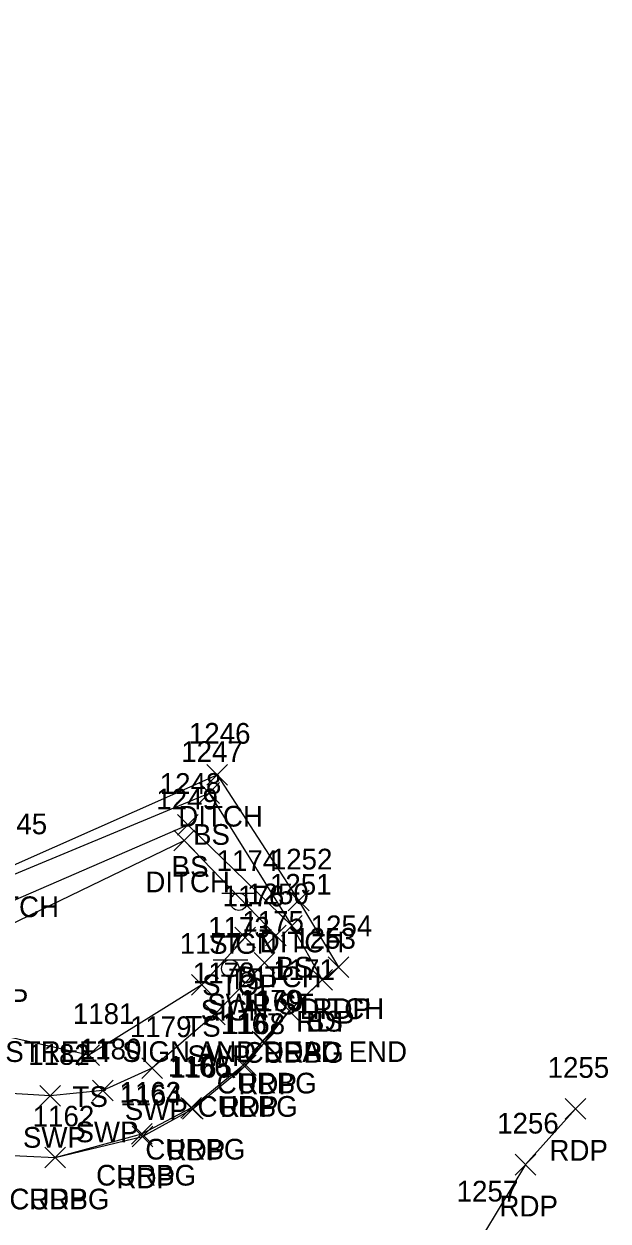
# Model space of a CAD drawing. Extents: x 1688195 to 1692013, y 424605 to 441234.
# Drawn here: x 1691954.3 to 1692010.6, y 439243.2 to 439358.8 of the extents above; entities that cross this region are included whole.
import ezdxf

# ---------------------------------------------------------------- set-up
doc = ezdxf.new("R2010")
doc.units = 0
for name, color, linetype in [('D_A', 7, 'Continuous'), ('D_C', 7, 'Continuous'), ('D_I', 7, 'Continuous'), ('D_TIC', 7, 'Continuous'), ('DD', 7, 'Continuous'), ('L_A', 7, 'Continuous'), ('L_I', 7, 'Continuous'), ('L_TIC', 7, 'Continuous'), ('LELB', 7, 'Continuous'), ('P_A', 7, 'Continuous'), ('P_I', 7, 'Continuous'), ('P_TIC', 7, 'Continuous'), ('PET', 7, 'Continuous'), ('R_A', 7, 'Continuous'), ('R_I', 7, 'Continuous'), ('R_TIC', 7, 'Continuous'), ('RC', 7, 'Continuous'), ('RSW', 7, 'Continuous'), ('S_A', 7, 'Continuous'), ('S_C', 7, 'Continuous'), ('S_I', 7, 'Continuous'), ('SSGN', 7, 'Continuous')]:
    doc.layers.add(name, color=color, linetype=linetype)

msp = doc.modelspace()

# ---------------------------------------------------------------- linework, layer by layer
at = {"layer": 'D_TIC'}
for points in [[(1691971.91, 439285.3), (1691973.91, 439287.3)], [(1691973.91, 439285.3), (1691971.91, 439287.3)], [(1691968.73, 439278.96), (1691970.73, 439280.96)], [(1691970.73, 439278.96), (1691968.73, 439280.96)], [(1691979.77, 439273.16), (1691981.77, 439275.16)], [(1691981.77, 439273.16), (1691979.77, 439275.16)], [(1691977.58, 439269.8), (1691979.58, 439271.8)], [(1691979.58, 439269.8), (1691977.58, 439271.8)], [(1691983.62, 439266.72), (1691985.62, 439268.72)], [(1691985.62, 439266.72), (1691983.62, 439268.72)]]:
    msp.add_lwpolyline(points, dxfattribs=at)
at = {"layer": 'DD'}
for points in [[(1691845, 439386.65), (1691846.96, 439371.91), (1691853.76, 439362.04), (1691874.03, 439339.66), (1691896.1, 439318.91), (1691934.44, 439282.93), (1691949.73, 439270.29), (1691969.73, 439279.96), (1691978.58, 439270.8)], [(1691849.48, 439383.4), (1691851.48, 439372.69), (1691857.96, 439364.8), (1691877.63, 439343.99), (1691899.36, 439321.57), (1691937.96, 439287.21), (1691947.81, 439278.16), (1691953.23, 439277.56), (1691972.91, 439286.3), (1691980.77, 439274.16), (1691984.62, 439267.72)]]:
    msp.add_lwpolyline(points, dxfattribs=at)
at = {"layer": 'L_TIC'}
for points in [[(1691971.13, 439283.54), (1691973.13, 439285.54)], [(1691973.13, 439283.54), (1691971.13, 439285.54)], [(1691969.06, 439280.46), (1691971.06, 439282.46)], [(1691971.06, 439280.46), (1691969.06, 439282.46)], [(1691979.12, 439270.73), (1691981.12, 439272.73)], [(1691981.12, 439270.73), (1691979.12, 439272.73)], [(1691979.12, 439270.73), (1691981.12, 439272.73)], [(1691981.12, 439270.73), (1691979.12, 439272.73)], [(1691974.61, 439269.6), (1691976.61, 439271.6)], [(1691976.61, 439269.6), (1691974.61, 439271.6)], [(1691970.42, 439265.02), (1691972.42, 439267.02)], [(1691972.42, 439265.02), (1691970.42, 439267.02)], [(1691982.03, 439265.51), (1691984.03, 439267.51)], [(1691984.03, 439265.51), (1691982.03, 439267.51)], [(1691959.53, 439258.24), (1691961.53, 439260.24)], [(1691961.53, 439258.24), (1691959.53, 439260.24)]]:
    msp.add_lwpolyline(points, dxfattribs=at)
at = {"layer": 'LELB'}
for points in [[(1691975.61, 439270.6), (1691971.42, 439266.02), (1691960.53, 439259.24), (1691939.22, 439264.04), (1691915.68, 439283.72), (1691886.97, 439308.05), (1691860.47, 439334.67), (1691845.99, 439348.3), (1691840.06, 439356.7), (1691834.35, 439370.12), (1691833.78, 439391.58)], [(1691846.65, 439384.74), (1691848.68, 439371.88), (1691855.16, 439363.03), (1691875.02, 439340.72), (1691897.71, 439320.03), (1691935.73, 439284.32), (1691949.05, 439272.37), (1691970.06, 439281.46), (1691980.12, 439271.73), (1691983.03, 439266.51)], [(1691847.58, 439384.47), (1691849.65, 439372.1), (1691856.36, 439363.87), (1691876.41, 439342.83), (1691898.4, 439320.72), (1691936.44, 439285.39), (1691950.07, 439275.35), (1691972.13, 439284.54), (1691980.12, 439271.73)]]:
    msp.add_lwpolyline(points, dxfattribs=at)
at = {"layer": 'P_TIC'}
for points in [[(1691983.62, 439266.72), (1691985.62, 439268.72)], [(1691985.62, 439266.72), (1691983.62, 439268.72)], [(1691982.03, 439265.51), (1691984.03, 439267.51)], [(1691984.03, 439265.51), (1691982.03, 439267.51)], [(1691978.88, 439262.5), (1691980.88, 439264.5)], [(1691980.88, 439262.5), (1691978.88, 439264.5)], [(1691976.47, 439259.47), (1691978.47, 439261.47)], [(1691978.47, 439259.47), (1691976.47, 439261.47)], [(1691974.68, 439257.27), (1691976.68, 439259.27)], [(1691976.68, 439257.27), (1691974.68, 439259.27)], [(1691969.56, 439253.07), (1691971.56, 439255.07)], [(1691971.56, 439253.07), (1691969.56, 439255.07)], [(1692006.49, 439253.05), (1692008.49, 439255.05)], [(1692008.49, 439253.05), (1692006.49, 439255.05)], [(1691964.7, 439250.38), (1691966.7, 439252.38)], [(1691966.7, 439250.38), (1691964.7, 439252.38)], [(1691956.26, 439248.35), (1691958.26, 439250.35)], [(1691958.26, 439248.35), (1691956.26, 439250.35)], [(1692001.68, 439247.67), (1692003.68, 439249.67)], [(1692003.68, 439247.67), (1692001.68, 439249.67)]]:
    msp.add_lwpolyline(points, dxfattribs=at)
at = {"layer": 'PET'}
for points in [[(1691876.93, 439304.47), (1691895.87, 439287.46), (1691912.05, 439273.82), (1691927.79, 439260.94), (1691934.43, 439255.64), (1691939.54, 439252.36), (1691945.3, 439250.2), (1691949.02, 439249.75), (1691957.26, 439249.35), (1691965.7, 439251.38), (1691970.56, 439254.07), (1691975.68, 439258.27), (1691977.47, 439260.47), (1691979.88, 439263.5), (1691983.03, 439266.51), (1691984.62, 439267.72)], [(1692007.49, 439254.05), (1692002.68, 439248.67), (1691998.71, 439242.11), (1691993.13, 439228.35), (1691994.88, 439222.81), (1691997.3, 439212.86), (1692000.21, 439206.28), (1692004.29, 439200.33), (1692010.35, 439194.63)]]:
    msp.add_lwpolyline(points, dxfattribs=at)
at = {"layer": 'R_TIC'}
for points in [[(1691976.46, 439267.16), (1691978.46, 439269.16)], [(1691978.46, 439267.16), (1691976.46, 439269.16)], [(1691971.67, 439262.18), (1691973.67, 439264.18)], [(1691973.67, 439262.18), (1691971.67, 439264.18)], [(1691978.88, 439262.5), (1691980.88, 439264.5)], [(1691980.88, 439262.5), (1691978.88, 439264.5)], [(1691976.27, 439259.54), (1691978.27, 439261.54)], [(1691978.27, 439259.54), (1691976.27, 439261.54)], [(1691965.62, 439256.98), (1691967.62, 439258.98)], [(1691967.62, 439256.98), (1691965.62, 439258.98)], [(1691974.43, 439257.29), (1691976.43, 439259.29)], [(1691976.43, 439257.29), (1691974.43, 439259.29)], [(1691955.78, 439254.3), (1691957.78, 439256.3)], [(1691957.78, 439254.3), (1691955.78, 439256.3)], [(1691960.86, 439254.83), (1691962.86, 439256.83)], [(1691962.86, 439254.83), (1691960.86, 439256.83)], [(1691969.39, 439253.16), (1691971.39, 439255.16)], [(1691971.39, 439253.16), (1691969.39, 439255.16)], [(1691964.64, 439250.65), (1691966.64, 439252.65)], [(1691966.64, 439250.65), (1691964.64, 439252.65)], [(1691956.26, 439248.35), (1691958.26, 439250.35)], [(1691958.26, 439248.35), (1691956.26, 439250.35)]]:
    msp.add_lwpolyline(points, dxfattribs=at)
at = {"layer": 'RC'}
msp.add_lwpolyline([(1691957.26, 439249.35), (1691965.64, 439251.65), (1691970.39, 439254.16), (1691975.43, 439258.29), (1691977.27, 439260.54), (1691979.88, 439263.5)], dxfattribs=at)
at = {"layer": 'RSW'}
msp.add_lwpolyline([(1691977.46, 439268.16), (1691972.67, 439263.18), (1691966.62, 439257.98), (1691961.86, 439255.83), (1691956.78, 439255.3), (1691947.57, 439255.86), (1691941.63, 439257.35), (1691936.74, 439260.66), (1691912.9, 439280.3), (1691884.49, 439305), (1691857.04, 439330.93), (1691842.61, 439345.6), (1691837.43, 439352.31), (1691833.75, 439359.53), (1691830.58, 439369.1), (1691830.34, 439383.86), (1691832.59, 439392.6)], dxfattribs=at)
at = {"layer": 'SSGN'}
for p, q in [((1691973.35, 439274.87), (1691976.68, 439274.87)), ((1691974.99, 439274.04), (1691974.99, 439274.04)), ((1691972.53, 439268.44), (1691975.86, 439268.44)), ((1691974.17, 439267.61), (1691974.17, 439267.61))]:
    msp.add_line(p, q, dxfattribs=at)
for centre in [(1691974.99, 439274.04), (1691974.17, 439267.61)]:
    msp.add_circle(centre, 0.833, dxfattribs=at)

# ---------------------------------------------------------------- texts
at = {"layer": 'D_A'}
for p in [(1691969.15, 439281.3), (1691965.97, 439274.96), (1691949.47, 439272.56), (1691977.01, 439269.16), (1691974.82, 439265.8), (1691980.86, 439262.72)]:
    msp.add_text('DITCH', height=2, dxfattribs=at).set_placement(p)
at = {"layer": 'D_C'}
msp.add_text('30 RCP', height=2, dxfattribs=at).set_placement((1691945.31, 439263.6))
at = {"layer": 'D_I'}
for s, p in [('1246', (1691970.17, 439289.3)), ('1249', (1691967.03, 439282.96)), ('1245', (1691950.54, 439280.56)), ('1252', (1691978.08, 439277.16)), ('1250', (1691975.8, 439273.8)), ('1254', (1691981.93, 439270.72))]:
    msp.add_text(s, height=2, dxfattribs=at).set_placement(p)
at = {"layer": 'L_A'}
for s, p in [('BS', (1691970.57, 439279.54)), ('BS', (1691968.5, 439276.46)), ('BS', (1691978.56, 439266.73)), ('BS', (1691978.56, 439266.73)), ('TS', (1691974.02, 439265.6)), ('TS', (1691969.83, 439261.02)), ('BS', (1691981.47, 439261.51)), ('TS', (1691958.94, 439254.24))]:
    msp.add_text(s, height=2, dxfattribs=at).set_placement(p)
at = {"layer": 'L_I'}
for s, p in [('1247', (1691969.43, 439287.54)), ('1248', (1691967.36, 439284.46)), ('1251', (1691978, 439274.73)), ('1251', (1691978, 439274.73)), ('1176', (1691973.43, 439273.6)), ('1253', (1691980.34, 439269.51)), ('1177', (1691969.29, 439269.02)), ('1181', (1691958.97, 439262.24))]:
    msp.add_text(s, height=2, dxfattribs=at).set_placement(p)
at = {"layer": 'P_A'}
for p in [(1691982.11, 439262.72), (1691980.52, 439261.51), (1691977.37, 439258.5), (1691974.95, 439255.47), (1691973.17, 439253.27), (1691968.04, 439249.07), (1692004.98, 439249.05), (1691963.19, 439246.38), (1691954.75, 439244.35), (1692000.16, 439243.67)]:
    msp.add_text('RDP', height=2, dxfattribs=at).set_placement(p)
at = {"layer": 'P_I'}
for s, p in [('1254', (1691981.93, 439270.72)), ('1253', (1691980.34, 439269.51)), ('1171', (1691978.32, 439266.5)), ('1169', (1691975.29, 439263.47)), ('1168', (1691973.51, 439261.27)), ('1165', (1691968.38, 439257.07)), ('1255', (1692004.8, 439257.05)), ('1164', (1691963.53, 439254.38)), ('1162', (1691955.09, 439252.35)), ('1256', (1691999.93, 439251.67)), ('1257', (1691996.02, 439245.11))]:
    msp.add_text(s, height=2, dxfattribs=at).set_placement(p)
at = {"layer": 'R_A'}
for s, p in [('SWP ST', (1691971.95, 439263.16)), ('SWP', (1691970.03, 439258.18)), ('CURBG', (1691975.47, 439258.5)), ('CURBG', (1691972.86, 439255.54)), ('SWP', (1691963.98, 439252.98)), ('CURBG', (1691971.02, 439253.29)), ('SWP', (1691959.22, 439250.83)), ('SWP', (1691954.15, 439250.3)), ('CURBG', (1691965.97, 439249.16)), ('CURBG', (1691961.22, 439246.65)), ('CURBG', (1691952.85, 439244.35))]:
    msp.add_text(s, height=2, dxfattribs=at).set_placement(p)
at = {"layer": 'R_I'}
for s, p in [('1175', (1691975.33, 439271.16)), ('1178', (1691970.55, 439266.18)), ('1171', (1691978.32, 439266.5)), ('1170', (1691975.06, 439263.54)), ('1179', (1691964.48, 439260.98)), ('1167', (1691973.26, 439261.29)), ('1180', (1691959.64, 439258.83)), ('1182', (1691954.66, 439258.3)), ('1166', (1691968.16, 439257.16)), ('1163', (1691963.47, 439254.65)), ('1162', (1691955.09, 439252.35))]:
    msp.add_text(s, height=2, dxfattribs=at).set_placement(p)
at = {"layer": 'S_A'}
for p in [(1691972.13, 439269.02), (1691971.31, 439262.58)]:
    msp.add_text('SIGN', height=2, dxfattribs=at).set_placement(p)
at = {"layer": 'S_C'}
for s, p in [('STOP', (1691971.45, 439265.02)), ('STREET SIGN AND DEAD END', (1691952.45, 439258.58))]:
    msp.add_text(s, height=2, dxfattribs=at).set_placement(p)
at = {"layer": 'S_I'}
for s, p in [('1174', (1691972.85, 439277.02)), ('1173', (1691972.03, 439270.58))]:
    msp.add_text(s, height=2, dxfattribs=at).set_placement(p)

doc.saveas('drawing.dxf')
